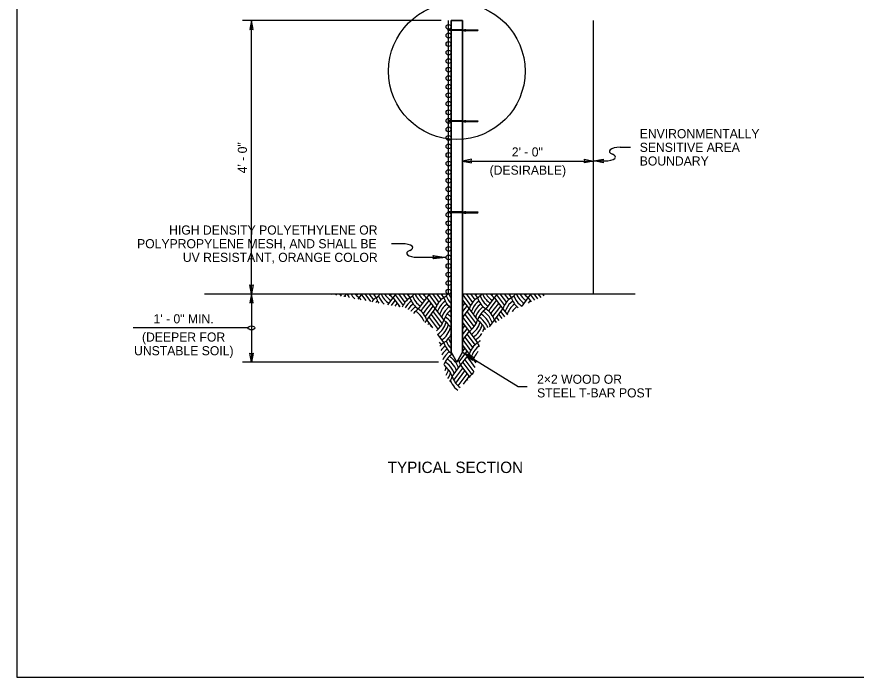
# Model space of a CAD drawing. Extents: x 99862 to 103151, y 100000 to 102076.
# Drawn here: x 99862 to 101337, y 100000 to 101160 of the extents above; entities that cross this region are included whole.
import ezdxf

# ---------------------------------------------------------------- set-up
doc = ezdxf.new("R2010")
doc.units = 0
for name, color, linetype in [('Level 1', 7, 'Continuous'), ('Level 10', 7, 'Continuous'), ('Level 11', 7, 'Continuous'), ('Level 14', 7, 'Continuous'), ('Level 15', 7, 'Continuous'), ('Level 20', 7, 'Continuous'), ('Level 31', 7, 'Continuous'), ('Level 38', 7, 'Continuous'), ('Level 6', 7, 'Continuous'), ('Level 60', 7, 'Continuous'), ('Level 7', 7, 'Continuous')]:
    doc.layers.add(name, color=color, linetype=linetype)

msp = doc.modelspace()

# ---------------------------------------------------------------- linework, layer by layer
at = {"layer": 'Level 1'}
msp.add_lwpolyline([(99862, 99999.5), (103151, 99999.5), (103151, 102075.5), (99862, 102075.5)], close=True, dxfattribs=at)
at = {"layer": 'Level 10'}
msp.add_lwpolyline([(100620.7, 100672.7), (100620.7, 101153.1)], dxfattribs=at)
for centre in [(100620.7, 101141.9), (100620.7, 101126.9), (100620.7, 101111.9), (100620.7, 101096.9), (100620.7, 101081.9), (100620.7, 101066.9), (100620.7, 101051.9), (100620.7, 101036.9), (100620.7, 101021.9), (100620.7, 101006.9), (100620.7, 100991.9), (100620.7, 100976.9), (100620.7, 100961.9), (100620.7, 100946.9), (100620.7, 100931.9), (100620.7, 100916.9), (100620.7, 100901.9), (100620.7, 100886.9), (100620.7, 100871.9), (100620.7, 100856.9), (100620.7, 100841.9), (100620.7, 100826.9), (100620.7, 100811.9), (100620.7, 100796.9), (100620.7, 100781.9), (100620.7, 100766.9), (100620.7, 100751.9), (100620.7, 100736.9), (100620.7, 100721.9), (100620.7, 100706.9), (100620.7, 100691.9), (100620.7, 100676.9)]:
    msp.add_circle(centre, 4.2, dxfattribs=at)
at = {"layer": 'Level 11'}
for p, q in [((100620.1, 101135.5), (100620.1, 101136.8)), ((100646.4, 101136.8), (100620.1, 101136.8)), ((100646.4, 101135.5), (100620.1, 101135.5)), ((100646.4, 101135.5), (100646.4, 101136.8)), ((100646.4, 101136.8), (100650.8, 101136.8)), ((100646.4, 101135.5), (100650.8, 101135.5)), ((100648.9, 101134.9), (100648.9, 101137.4)), ((100648.9, 101137.4), (100651.4, 101137.4)), ((100648.9, 101134.9), (100651.4, 101134.9)), ((100649.6, 101135.2), (100649.6, 101137.1)), ((100649.6, 101137.1), (100650.8, 101137.1)), ((100649.6, 101135.2), (100650.8, 101135.2)), ((100649.9, 101135.5), (100649.9, 101136.8)), ((100650.8, 101135.2), (100650.8, 101137.1)), ((100651.4, 101134.9), (100651.4, 101137.4)), ((100651.4, 101136.8), (100672, 101136.8)), ((100651.4, 101135.5), (100672, 101135.5)), ((100672, 101136.8), (100672.2, 101136.7)), ((100672, 101135.5), (100672.2, 101135.6)), ((100620.1, 100975.5), (100620.1, 100976.8)), ((100646.4, 100976.8), (100620.1, 100976.8)), ((100646.4, 100975.5), (100620.1, 100975.5)), ((100646.4, 100975.5), (100646.4, 100976.8)), ((100646.4, 100976.8), (100650.8, 100976.8)), ((100646.4, 100975.5), (100650.8, 100975.5)), ((100648.9, 100974.9), (100648.9, 100977.4)), ((100648.9, 100977.4), (100651.4, 100977.4)), ((100648.9, 100974.9), (100651.4, 100974.9)), ((100649.6, 100975.2), (100649.6, 100977.1)), ((100649.6, 100977.1), (100650.8, 100977.1)), ((100649.6, 100975.2), (100650.8, 100975.2)), ((100649.9, 100975.5), (100649.9, 100976.8)), ((100650.8, 100975.2), (100650.8, 100977.1)), ((100651.4, 100974.9), (100651.4, 100977.4)), ((100651.4, 100976.8), (100672, 100976.8)), ((100651.4, 100975.5), (100672, 100975.5)), ((100672, 100976.8), (100672.2, 100976.7)), ((100672, 100975.5), (100672.2, 100975.6)), ((100620.1, 100815.5), (100620.1, 100816.8)), ((100646.4, 100816.8), (100620.1, 100816.8)), ((100646.4, 100815.5), (100620.1, 100815.5)), ((100646.4, 100815.5), (100646.4, 100816.8)), ((100646.4, 100816.8), (100650.8, 100816.8)), ((100646.4, 100815.5), (100650.8, 100815.5)), ((100648.9, 100814.9), (100648.9, 100817.4)), ((100648.9, 100817.4), (100651.4, 100817.4)), ((100648.9, 100814.9), (100651.4, 100814.9)), ((100649.6, 100815.2), (100649.6, 100817.1)), ((100649.6, 100817.1), (100650.8, 100817.1)), ((100649.6, 100815.2), (100650.8, 100815.2)), ((100649.9, 100815.5), (100649.9, 100816.8)), ((100650.8, 100815.2), (100650.8, 100817.1)), ((100651.4, 100814.9), (100651.4, 100817.4)), ((100651.4, 100816.8), (100672, 100816.8)), ((100651.4, 100815.5), (100672, 100815.5)), ((100672, 100816.8), (100672.2, 100816.7)), ((100672, 100815.5), (100672.2, 100815.6))]:
    msp.add_line(p, q, dxfattribs=at)
for centre in [(100671.9, 101136.1), (100671.9, 100976.1), (100671.9, 100816.1)]:
    msp.add_arc(centre, 0.624, 300, 60, dxfattribs=at)
at = {"layer": 'Level 14'}
for p, q in [((100922.1, 100930.4), (100940.7, 100930.4)), ((100876.7, 100906.4), (100895.4, 100906.4)), ((100539.1, 100761.1), (100520.5, 100761.1)), ((100616.5, 100737.1), (100565.8, 100737.1))]:
    msp.add_line(p, q, dxfattribs=at)
for points in [[(100876.7, 100906.4), (100892.4, 100909.5), (100891.7, 100906.4), (100892.4, 100903.3)], [(100616.5, 100737.1), (100593.7, 100734.2), (100594.8, 100737.1), (100593.7, 100740.1)]]:
    msp.add_lwpolyline(points, close=True, dxfattribs=at)
for centre, major_axis, start_param, end_param in [((100921.9, 100923.4), (-18.7, 0), 4.705244, 7.068624), ((100895.4, 100913.5), (-18.7, 0), 1.570796, 3.926959), ((100539.3, 100754.1), (18.7, 0), 5.497747, 7.861127), ((100565.8, 100744.2), (18.7, 0), 2.356226, 4.712389)]:
    msp.add_ellipse(centre, major_axis=major_axis, ratio=0.375, start_param=start_param, end_param=end_param, dxfattribs=at)
at = {"layer": 'Level 15'}
for p, q in [((100607.9, 101153.1), (100258.4, 101153.1)), ((100274.4, 100673.1), (100274.4, 101153.1)), ((100645.2, 100906.3), (100875.2, 100906.3)), ((100274.4, 100673.1), (100274.4, 100553.1)), ((100645.2, 100570.5), (100742.8, 100510.5)), ((100603.2, 100553.1), (100258.4, 100553.1)), ((100742.8, 100510.5), (100758.8, 100510.5))]:
    msp.add_line(p, q, dxfattribs=at)
for points in [[(100274.4, 101153.1), (100271.3, 101137.4), (100274.4, 101138.1), (100277.5, 101137.4)], [(100645.2, 100906.3), (100660.9, 100903.2), (100660.2, 100906.3), (100660.9, 100909.4)], [(100875.2, 100906.3), (100859.5, 100903.2), (100860.2, 100906.3), (100859.5, 100909.4)], [(100274.4, 100673.1), (100271.3, 100688.9), (100274.4, 100688.1), (100277.5, 100688.9)], [(100274.4, 100673.1), (100271.3, 100657.4), (100274.4, 100658.1), (100277.5, 100657.4)], [(100274.4, 100553.1), (100271.3, 100568.9), (100274.4, 100568.1), (100277.5, 100568.9)], [(100645.2, 100570.5), (100666.2, 100561.1), (100663.7, 100559.1), (100663.1, 100556)]]:
    msp.add_lwpolyline(points, close=True, dxfattribs=at)
msp.add_circle((100635.2, 101064), 120, dxfattribs=at)
msp.add_ellipse((100274.4, 100613.1), major_axis=(-6, 0), ratio=0.57735, dxfattribs=at)
at = {"layer": 'Level 31'}
msp.add_line((100875.2, 100673.1), (100875.2, 101153), dxfattribs=at)
at = {"layer": 'Level 38'}
for p, q in [((100625.2, 100570.5), (100625.2, 101153.1)), ((100625.2, 101153.1), (100645.2, 101153.1)), ((100645.2, 101153.1), (100625.2, 101153.1)), ((100625.2, 101153.1), (100625.2, 100570.5)), ((100645.2, 101153.1), (100645.2, 100570.5)), ((100645.2, 100570.5), (100645.2, 101153.1)), ((100635.2, 100553.1), (100625.2, 100570.5)), ((100625.2, 100570.5), (100635.2, 100553.1)), ((100645.2, 100570.5), (100635.2, 100553.1)), ((100635.2, 100553.1), (100645.2, 100570.5))]:
    msp.add_line(p, q, dxfattribs=at)
at = {"layer": 'Level 6'}
for p, q in [((100191.9, 100673.1), (100625.2, 100673.1)), ((100645.2, 100673.1), (100948.9, 100673.1))]:
    msp.add_line(p, q, dxfattribs=at)
at = {"layer": 'Level 60'}
msp.add_line((99862, 99999.5), (99862, 99999.5), dxfattribs=at)
at = {"layer": 'Level 7'}
for p, q in [((100409.6, 100673), (100409.7, 100673.1)), ((100414.1, 100673.1), (100415, 100672)), ((100421.5, 100673.1), (100423.6, 100670.4)), ((100428.9, 100673.1), (100432.2, 100668.8)), ((100459.2, 100669.9), (100461.7, 100673.1)), ((100461.8, 100663.4), (100463.9, 100666.2)), ((100463.9, 100666.2), (100469.1, 100673.1)), ((100463.9, 100666.2), (100466.6, 100662.6)), ((100467.6, 100671.1), (100475.2, 100661)), ((100473.5, 100673.1), (100483.8, 100659.4)), ((100480.9, 100673.1), (100488.9, 100662.5)), ((100488.3, 100673.1), (100493.6, 100666.2)), ((100514.1, 100653.9), (100523.3, 100666.2)), ((100518.6, 100669.9), (100521.1, 100673.1)), ((100523.3, 100666.2), (100528.5, 100673.1)), ((100523.3, 100666.2), (100535.4, 100650)), ((100527, 100671.1), (100540.8, 100652.7)), ((100532.9, 100673.1), (100544.2, 100658)), ((100540.3, 100673.1), (100548.3, 100662.5)), ((100547.7, 100673.1), (100553, 100666.2)), ((100567.8, 100646.4), (100582.7, 100666.2)), ((100578, 100669.9), (100580.5, 100673.1)), ((100582.7, 100666.2), (100587.9, 100673.1)), ((100582.7, 100666.2), (100597.5, 100646.4)), ((100586.4, 100671.1), (100600.2, 100652.7)), ((100592.3, 100673.1), (100603.6, 100658)), ((100599.7, 100673.1), (100607.7, 100662.5)), ((100607.1, 100673.1), (100612.4, 100666.2)), ((100645.2, 100670.4), (100647.3, 100673.1)), ((100645.8, 100671.1), (100659.6, 100652.7)), ((100651.7, 100673.1), (100663, 100658)), ((100659.1, 100673.1), (100667.1, 100662.5)), ((100666.5, 100673.1), (100671.7, 100666.2)), ((100686.6, 100646.4), (100701.4, 100666.2)), ((100696.8, 100669.9), (100699.3, 100673.1)), ((100701.4, 100666.2), (100706.7, 100673.1)), ((100701.4, 100666.2), (100716.3, 100646.4)), ((100705.2, 100671.1), (100719, 100652.7)), ((100711.1, 100673.1), (100722.4, 100658)), ((100718.5, 100673.1), (100726.5, 100662.5)), ((100725.9, 100673.1), (100731.1, 100666.2)), ((100749.9, 100651.6), (100760.8, 100666.2)), ((100756.2, 100669.9), (100758.6, 100673.1)), ((100760.8, 100666.2), (100766.1, 100673.1)), ((100760.8, 100666.2), (100766.2, 100659)), ((100764.6, 100671.1), (100771.7, 100661.6)), ((100770.5, 100673.1), (100777.2, 100664.1)), ((100777.9, 100673.1), (100782.8, 100666.6)), ((100785.3, 100673.1), (100788.3, 100669.2)), ((100520.6, 100652.7), (100527, 100661.2)), ((100527.1, 100651.5), (100530.7, 100656.3)), ((100533.6, 100650.3), (100534.4, 100651.3)), ((100575.2, 100646.4), (100586.4, 100661.2)), ((100582.7, 100646.4), (100590.1, 100656.3)), ((100590.1, 100646.4), (100593.8, 100651.3)), ((100645.2, 100662), (100656.9, 100646.4)), ((100645.2, 100660.5), (100645.8, 100661.2)), ((100645.2, 100650.6), (100649.5, 100656.3)), ((100649.5, 100646.4), (100653.2, 100651.3)), ((100694, 100646.4), (100705.2, 100661.2)), ((100701.4, 100646.4), (100708.9, 100656.3)), ((100708.9, 100646.4), (100712.6, 100651.3)), ((100761.2, 100656.8), (100764.6, 100661.2)), ((100572.5, 100642.7), (100575.2, 100646.4)), ((100576.5, 100638.2), (100582.7, 100646.4)), ((100580, 100632.9), (100590.1, 100646.4)), ((100582.7, 100626.6), (100597.5, 100646.4)), ((100590.1, 100636.5), (100606.2, 100614.9)), ((100593.8, 100641.4), (100609.7, 100620.2)), ((100597.5, 100646.4), (100612.4, 100626.6)), ((100645.2, 100640.7), (100649.5, 100646.4)), ((100645.2, 100630.8), (100656.9, 100646.4)), ((100649.5, 100636.5), (100665.6, 100614.9)), ((100653.2, 100641.4), (100669.1, 100620.2)), ((100656.9, 100646.4), (100671.7, 100626.6)), ((100691.3, 100642.7), (100694, 100646.4)), ((100695.3, 100638.2), (100701.4, 100646.4)), ((100698.8, 100632.9), (100708.9, 100646.4)), ((100701.4, 100626.6), (100716.3, 100646.4)), ((100708.9, 100636.5), (100714.2, 100629.4)), ((100712.6, 100641.4), (100719.1, 100632.7)), ((100716.3, 100646.4), (100724.1, 100636)), ((100579.8, 100622.8), (100582.7, 100626.6)), ((100582.7, 100626.6), (100592.5, 100613.4)), ((100584.6, 100619.3), (100586.4, 100621.6)), ((100586.4, 100631.5), (100602.2, 100610.5)), ((100645.2, 100622.4), (100656.9, 100606.8)), ((100645.2, 100620.9), (100645.8, 100621.6)), ((100645.8, 100631.5), (100661.6, 100610.5)), ((100692.7, 100614.9), (100701.4, 100626.6)), ((100701.4, 100626.6), (100704.3, 100622.7)), ((100705.2, 100631.5), (100709.3, 100626)), ((100268.4, 100613.1), (100066.4, 100613.1)), ((100589.4, 100615.7), (100590.1, 100616.7)), ((100645.2, 100611), (100649.5, 100616.7)), ((100645.2, 100601.1), (100653.2, 100611.7)), ((100645.2, 100591.2), (100656.9, 100606.8)), ((100656.9, 100606.8), (100671.7, 100587)), ((100601.3, 100601.7), (100612.4, 100587)), ((100645.8, 100591.9), (100659.6, 100573.5)), ((100649.5, 100596.9), (100663, 100578.8)), ((100653.2, 100601.8), (100667.1, 100583.3)), ((100604.2, 100587.9), (100607.7, 100583.3)), ((100645.2, 100582.8), (100656.9, 100567.2)), ((100645.2, 100581.3), (100645.8, 100582)), ((100645.2, 100571.4), (100649.5, 100577.1)), ((100639.4, 100553.7), (100649.5, 100567.2)), ((100642, 100547.4), (100656.9, 100567.2)), ((100649.5, 100567.2), (100653.2, 100572.1)), ((100653.2, 100562.2), (100667, 100543.8)), ((100656.9, 100567.2), (100668.6, 100551.6)), ((100627.2, 100527.6), (100642, 100547.4)), ((100642, 100547.4), (100656.9, 100527.6)), ((100645.8, 100552.3), (100661.6, 100531.3)), ((100649.5, 100557.3), (100665.4, 100536)), ((100629.9, 100521.2), (100645.8, 100542.4)), ((100633.3, 100515.9), (100649.5, 100537.5)), ((100637.4, 100511.5), (100653.2, 100532.5)), ((100647.1, 100514.5), (100656.9, 100527.6)), ((100649.5, 100517.7), (100649.8, 100517.3)), ((100653.2, 100522.6), (100654, 100521.6)), ((100656.9, 100527.6), (100658.2, 100525.9))]:
    msp.add_line(p, q, dxfattribs=at)
for centre, start, end in [((100409.5, 100702.3), 303.9036, 309.1011), ((100413.2, 100697.4), 308.6645, 319.8858), ((100473.7, 100682.5), 200.2432, 203.4498), ((100477.4, 100687.5), 202.3876, 214.3649), ((100481.1, 100692.4), 210.8366, 211.332), ((100481.1, 100692.4), 211.3319, 227.9542), ((100484.8, 100697.4), 220.1142, 236.0964), ((100514.5, 100635), 123.9036, 140.1158), ((100468.9, 100702.3), 303.9036, 309.1011), ((100472.6, 100697.4), 303.9036, 319.8858), ((100529.4, 100677.6), 197.6434, 213.4876), ((100533.1, 100682.5), 200.2432, 226.7788), ((100536.8, 100687.5), 202.3876, 220.9416), ((100540.5, 100692.4), 210.8366, 211.332), ((100540.5, 100692.4), 211.3319, 236.0964), ((100536.8, 100687.5), 220.9415, 236.0964), ((100544.2, 100697.4), 220.1142, 236.0964), ((100573.9, 100635), 123.9036, 157.5709), ((100528.3, 100702.3), 303.9036, 309.1011), ((100532, 100697.4), 303.9036, 319.8858), ((100588.8, 100677.6), 197.6434, 236.0964), ((100592.5, 100682.5), 200.2432, 228.9599), ((100596.2, 100687.5), 202.3876, 220.9416), ((100599.9, 100692.4), 210.8366, 211.332), ((100599.9, 100692.4), 211.3319, 236.0964), ((100596.2, 100687.5), 220.9415, 236.0964), ((100603.6, 100697.4), 220.1142, 236.0964), ((100633.3, 100635), 123.9036, 162.3566), ((100587.7, 100702.3), 303.9036, 309.1011), ((100591.4, 100697.4), 303.9036, 319.8858), ((100648.2, 100677.6), 197.6434, 232.3059), ((100651.9, 100682.5), 200.2432, 224.7458), ((100655.6, 100687.5), 202.3876, 215.9989), ((100692.7, 100635), 123.9036, 162.3566), ((100647.1, 100702.3), 303.9036, 309.1011), ((100650.8, 100697.4), 303.9036, 319.8858), ((100707.6, 100677.6), 197.6434, 236.0964), ((100711.3, 100682.5), 200.2432, 228.9599), ((100715, 100687.5), 202.3876, 220.9416), ((100718.7, 100692.4), 210.8366, 211.332), ((100718.7, 100692.4), 211.3319, 236.0964), ((100715, 100687.5), 220.9415, 236.0964), ((100722.4, 100697.4), 220.1142, 236.0964), ((100752.1, 100635), 123.9036, 162.3566), ((100706.5, 100702.3), 303.9036, 309.1011), ((100710.2, 100697.4), 303.9036, 319.8858), ((100767, 100677.6), 197.6434, 230.6192), ((100770.7, 100682.5), 200.2432, 228.9599), ((100774.4, 100687.5), 202.3876, 220.9416), ((100778.1, 100692.4), 210.8366, 211.332), ((100778.1, 100692.4), 211.3319, 236.0964), ((100774.4, 100687.5), 220.9415, 236.0964), ((100781.8, 100697.4), 220.1142, 236.0964), ((100765.9, 100702.3), 303.9036, 309.1011), ((100518.2, 100630), 126.3063, 132.4347), ((100577.6, 100630), 126.3063, 150.9192), ((100581.3, 100625.1), 127.1006, 145.4911), ((100585.1, 100620.1), 126.331, 135.7128), ((100592.5, 100682.5), 228.9599, 236.0964), ((100637, 100630), 126.3063, 154.2266), ((100640.7, 100625.1), 127.1006, 145.4911), ((100644.4, 100620.1), 126.331, 135.7128), ((100696.4, 100630), 126.3063, 154.2266), ((100700.1, 100625.1), 127.1006, 145.4911), ((100703.8, 100620.1), 126.331, 135.7128), ((100711.3, 100682.5), 228.9599, 236.0964), ((100755.8, 100630), 126.3063, 154.2266), ((100759.5, 100625.1), 127.1006, 145.4911), ((100763.2, 100620.1), 126.331, 135.7128), ((100770.7, 100682.5), 228.9599, 235.7628), ((100581.3, 100625.1), 145.491, 147.5541), ((100585.1, 100620.1), 135.7127, 144.8623), ((100588.8, 100615.2), 123.9036, 142.1737), ((100543.1, 100610.2), 48.9597, 58.5465), ((100546.8, 100615.2), 17.6434, 56.0963), ((100543.1, 100610.2), 21.776, 48.9597), ((100637, 100630), 154.2265, 162.3566), ((100640.7, 100625.1), 145.491, 162.3566), ((100644.4, 100620.1), 135.7127, 162.3566), ((100648.2, 100615.2), 127.6941, 162.3566), ((100598.8, 100605.3), 45.434, 59.3021), ((100602.5, 100610.2), 52.9193, 58.5465), ((100696.4, 100630), 154.2265, 162.3566), ((100700.1, 100625.1), 145.491, 162.3566), ((100703.8, 100620.1), 135.7127, 162.3566), ((100707.6, 100615.2), 123.9036, 162.3566), ((100658.2, 100605.3), 40.9413, 59.3021), ((100661.9, 100610.2), 48.9597, 58.5465), ((100665.6, 100615.2), 17.6434, 56.0963), ((100661.9, 100610.2), 17.6434, 48.9597), ((100755.8, 100630), 154.2265, 162.3566), ((100759.5, 100625.1), 145.491, 162.3566), ((100763.2, 100620.1), 135.7127, 145.1838), ((100576.5, 100638), 307.6955, 342.3566), ((100580.3, 100633), 303.9884, 345.0113), ((100584, 100628.1), 303.9036, 346.3199), ((100591.4, 100595.4), 25.9321, 56.0964), ((100595.1, 100600.3), 36.8201, 58.4874), ((100635.9, 100638), 303.9036, 342.3566), ((100639.7, 100633), 303.9036, 345.0113), ((100643.4, 100628.1), 303.9036, 346.3199), ((100650.8, 100595.4), 22.9286, 56.0964), ((100654.5, 100600.3), 31.3316, 58.4874), ((100658.2, 100605.3), 17.6434, 40.9414), ((100654.5, 100600.3), 19.7421, 31.3317), ((100587.7, 100623.1), 303.9036, 345.7713), ((100647.1, 100623.1), 334.8231, 345.7713), ((100591.4, 100618.2), 303.9036, 334.0679), ((100651.9, 100603.3), 200.2432, 224.7458), ((100655.6, 100608.3), 201.4344, 215.9989), ((100659.3, 100613.2), 200.8778, 204.7943), ((100647.1, 100623.1), 303.9036, 328.2682), ((100650.8, 100618.2), 303.9036, 313.1452), ((100711.3, 100603.3), 200.2432, 201.3171), ((100633.3, 100555.8), 123.9036, 137.4638), ((100637, 100550.8), 126.3063, 142.5202), ((100640.7, 100545.9), 127.1006, 145.4911), ((100648.2, 100598.4), 197.6434, 235.7545), ((100692.7, 100555.8), 123.9036, 162.3566), ((100696.4, 100550.8), 126.3063, 154.2266), ((100707.6, 100598.4), 197.6434, 208.1815), ((100640.7, 100545.9), 145.491, 147.9933), ((100644.4, 100540.9), 135.7127, 154.0755), ((100648.2, 100536), 124.0534, 161.139), ((100644.4, 100540.9), 126.331, 135.7128), ((100602.5, 100531), 48.9597, 58.5465), ((100696.4, 100550.8), 154.2265, 162.3566), ((100700.1, 100545.9), 145.491, 162.3566), ((100700.1, 100545.9), 137.1664, 145.4911), ((100591.4, 100516.2), 17.6434, 55.2112), ((100595.1, 100521.1), 31.3316, 58.4874), ((100598.8, 100526.1), 40.9413, 59.3021), ((100602.5, 100531), 17.6434, 48.9597), ((100598.8, 100526.1), 17.6434, 40.9414), ((100606.2, 100536), 17.6434, 33.9722), ((100703.8, 100540.9), 156.1329, 162.3566), ((100580.3, 100553.8), 336.1176, 345.0113), ((100584, 100548.9), 329.7869, 346.3199), ((100587.7, 100543.9), 328.4005, 345.7713), ((100595.1, 100521.1), 17.6434, 31.3317), ((100635.9, 100558.8), 303.9036, 321.2771), ((100591.4, 100539), 327.5108, 342.3566), ((100659.3, 100534), 200.8778, 211.332), ((100663, 100539), 197.6435, 234.4353), ((100659.3, 100534), 211.3319, 233.2209)]:
    msp.add_arc(centre, 37.6, start, end, dxfattribs=at)

# ---------------------------------------------------------------- texts
at = {"layer": 'Level 15'}
for s, p in [('ENVIRONMENTALLY', (100956.7, 100946.4)), ('2\' - 0"', (100731.9, 100914.3)), ('SENSITIVE AREA', (100956.7, 100922.4)), ('BOUNDARY', (100956.7, 100898.4)), ('(DESIRABLE)', (100692.9, 100882.3)), ('HIGH DENSITY POLYETHYLENE OR', (100129.7, 100777.1)), ('POLYPROPYLENE MESH, AND SHALL BE', (100073.4, 100753.1)), ('UV RESISTANT, ORANGE COLOR', (100153.8, 100729.1)), ('2×2 WOOD OR', (100776.3, 100515)), ('STEEL T-BAR POST', (100776.3, 100491))]:
    msp.add_text(s, height=16, dxfattribs=at).set_placement(p)
for s, rotation, p in [('4\' - 0"', 90, (100266.4, 100884.8)), ('1\' - 0" MIN.', 360, (100102.3, 100621.1)), ('(DEEPER FOR', 360, (100082, 100589.1)), ('UNSTABLE SOIL)', 360, (100068.1, 100565.1))]:
    msp.add_text(s, height=16, rotation=rotation, dxfattribs=at).set_placement(p)
at = {"layer": 'Level 20'}
msp.add_text('TYPICAL SECTION', height=20, dxfattribs=at).set_placement((100513.9, 100358.2))

doc.saveas('drawing.dxf')
